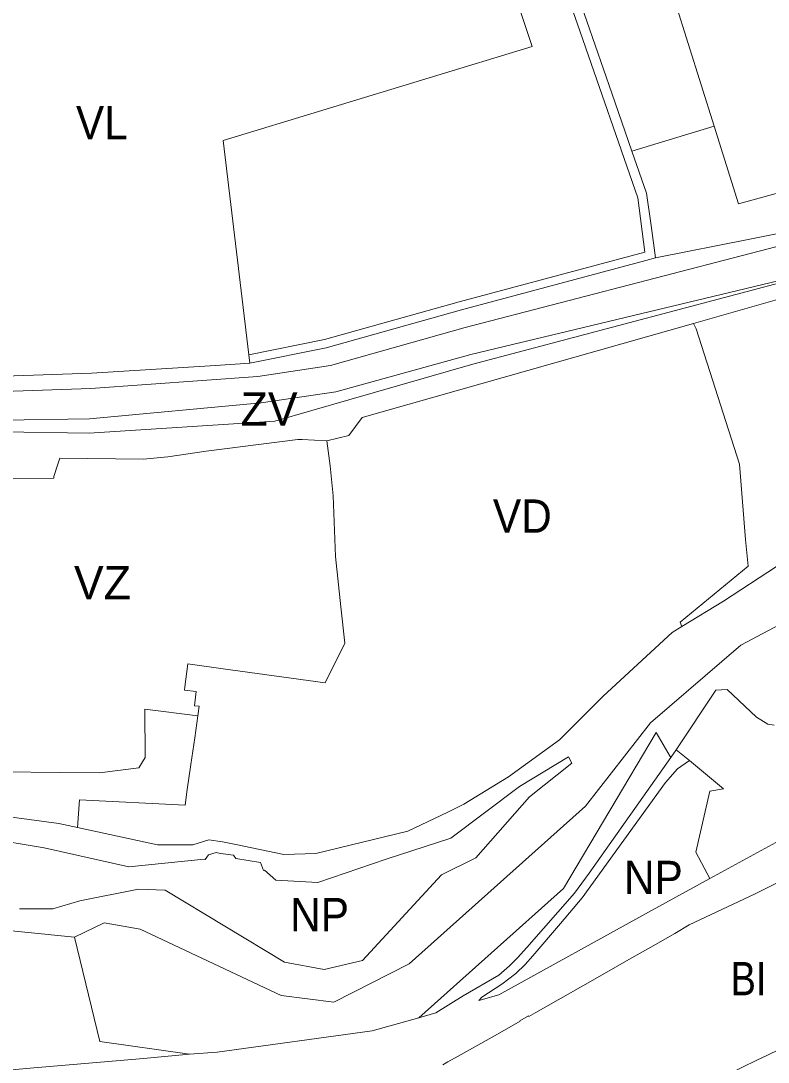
# Model space of a CAD drawing. Extents: x -650451 to -642268, y -1075216 to -1066610.
# Drawn here: x -646618.6 to -646349.6, y -1070484.4 to -1070109.3 of the extents above; entities that cross this region are included whole.
import ezdxf

# ---------------------------------------------------------------- set-up
doc = ezdxf.new("R2010")
doc.units = 0
doc.header["$LTSCALE"] = 4.8
for name, color, linetype, lineweight in [('15', 7, 'Continuous', 13), ('2', 7, 'Continuous', 13), ('31', 7, 'Continuous', 13), ('34', 7, 'Continuous', 13), ('35', 7, 'Continuous', 13), ('36', 7, 'Continuous', 13), ('40', 7, 'Continuous', 13), ('41', 7, 'Continuous', 13), ('45', 7, 'Continuous', 13), ('48', 7, 'Continuous', 13)]:
    doc.layers.add(name, color=color, linetype=linetype, lineweight=lineweight)
doc.layers.add('62', color=7, linetype='Continuous')

msp = doc.modelspace()

# ---------------------------------------------------------------- linework, layer by layer
at = {"layer": '15'}
for points in [[(-646536.47, -1070229.65), (-646509.31, -1070224.11), (-646460.8, -1070210.57), (-646393.97, -1070192.69), (-646396.51, -1070173.06), (-646417.23, -1070113.25), (-646424.17, -1070093.21), (-646446.21, -1070040.55), (-646450.22, -1070034.31), (-646445.81, -1070032.61)], [(-646445.81, -1070032.61), (-646420.85, -1070091.97), (-646405.85, -1070135.4), (-646398.64, -1070156.247)], [(-646173.2, -1070135.64), (-646227.29, -1070176.24), (-646274.26, -1070199.6), (-646291.14, -1070202.1), (-646315.95, -1070201.09), (-646376.5, -1070218.32)], [(-646398.64, -1070156.247), (-646393.4, -1070171.4), (-646391.75, -1070183.07), (-646390.1, -1070194.72)], [(-646705.52, -1070252.93), (-646625.33, -1070257.3), (-646594.04, -1070257.81), (-646527.17, -1070253.5), (-646500.57, -1070245.86), (-646455.89, -1070233.03), (-646311.02, -1070194.52)], [(-646390.1, -1070194.72), (-646393.58, -1070195.67), (-646459.99, -1070213.46), (-646508.71, -1070227.05), (-646536.11, -1070232.63), (-646536.47, -1070229.65)], [(-646376.5, -1070218.32), (-646495.71, -1070252.24), (-646500.58, -1070258.69), (-646508.45, -1070260.55)], [(-646508.45, -1070260.55), (-646517.36, -1070260.11), (-646518.94, -1070260.15), (-646551.91, -1070264.36), (-646565.72, -1070266.39), (-646574.52, -1070267.25), (-646604.59, -1070266.85), (-646605.28, -1070268.94), (-646606.76, -1070273.38), (-646606.75, -1070274.01), (-646653.15, -1070274.4), (-646660.11, -1070274.42), (-646660.07, -1070282.1), (-646649.84, -1070282.04), (-646649.55, -1070292.05)], [(-646647.05, -1070378.42), (-646647.02, -1070379.59), (-646604.46, -1070380.06), (-646590.31, -1070380.22), (-646576.16, -1070378.42), (-646573.88, -1070374.62), (-646574, -1070357.2), (-646554.86, -1070359.63)], [(-646554.86, -1070359.63), (-646556, -1070367.59), (-646557.42, -1070377.22), (-646558.74, -1070386.15), (-646559.41, -1070391.82), (-646597.44, -1070389.891), (-646598.16, -1070399.85)], [(-646370.56, -1070418.29), (-646344.26, -1070403.84), (-646336.35, -1070400.9), (-646225.15, -1070359.46)], [(-646475.345, -1070468.371), (-646469.235, -1070466.633), (-646459.41, -1070460.54), (-646446.59, -1070453), (-646442.72, -1070449.73), (-646439.83, -1070446.77), (-646436.48, -1070443.08), (-646419.34, -1070423.57), (-646414.01, -1070416.27), (-646384.62, -1070374.69), (-646382.67, -1070371.94), (-646377.86, -1070375.71)], [(-646377.86, -1070375.71), (-646378.32, -1070375.94), (-646382.19, -1070378.71), (-646386.6, -1070383.69), (-646416.56, -1070425.24), (-646424.34, -1070434.41), (-646434.35, -1070446.09), (-646437.1, -1070449.26), (-646440.39, -1070452.44), (-646445.45, -1070456.28), (-646452.6, -1070460.94), (-646453.736, -1070462.223), (-646446.536, -1070460.175), (-646392.61, -1070430.4), (-646370.56, -1070418.29)], [(-646598.16, -1070399.85), (-646604.96, -1070398.38), (-646641.54, -1070393.52), (-646652.04, -1070394.45)], [(-646325.23, -1070409.14), (-646354.31, -1070423.77), (-646378, -1070434.94), (-646383.22, -1070438.09), (-646391.82, -1070442.99), (-646400.54, -1070447.94), (-646404.52, -1070450.21), (-646413.57, -1070455.34), (-646433.25, -1070466.56), (-646435.74, -1070467.94), (-646435.86, -1070467.72), (-646438.98, -1070469.49), (-646438.88, -1070469.65), (-646446.97, -1070474.26), (-646461.19, -1070482.25), (-646464.9, -1070484.28), (-646466.68, -1070485.32)], [(-646557.82, -1070481.45), (-646547.87, -1070480.73), (-646492.113, -1070473.143), (-646475.345, -1070468.371)], [(-646364.46, -1070489.01), (-646353.63, -1070483.68), (-646350.05, -1070481.97), (-646336.58, -1070475.39)], [(-646653.92, -1070489.99), (-646646.34, -1070489.41), (-646617.87, -1070486.74), (-646616.63, -1070486.62), (-646574.42, -1070483.09), (-646557.82, -1070481.45)]]:
    msp.add_lwpolyline(points, dxfattribs=at)
at = {"layer": '2'}
for points in [[(-646466.68, -1070485.32), (-646464.9, -1070484.28), (-646461.19, -1070482.25), (-646446.97, -1070474.26), (-646438.88, -1070469.65), (-646438.98, -1070469.49), (-646435.86, -1070467.72), (-646435.74, -1070467.94), (-646433.25, -1070466.56), (-646413.57, -1070455.34), (-646404.52, -1070450.21), (-646400.54, -1070447.94), (-646391.82, -1070442.99), (-646383.22, -1070438.09), (-646378, -1070434.94), (-646354.31, -1070423.77), (-646325.23, -1070409.14)], [(-646336.58, -1070475.39), (-646350.05, -1070481.97), (-646353.63, -1070483.68), (-646364.46, -1070489.01)]]:
    msp.add_lwpolyline(points, dxfattribs=at)
at = {"layer": '31'}
for points in [[(-646369.042, -1070147.243), (-646383.07, -1070102.64), (-646400.77, -1070045.26), (-646401.69, -1070042.26), (-646409.27, -1070017.68)], [(-646215.99, -1070118.79), (-646225.41, -1070126.72), (-646245.94, -1070139.49), (-646266.83, -1070149.27), (-646298.56, -1070158.26), (-646360.23, -1070175.26), (-646369.042, -1070147.243)]]:
    msp.add_lwpolyline(points, dxfattribs=at)
at = {"layer": '34'}
for points in [[(-646409.27, -1070017.68), (-646401.69, -1070042.26), (-646400.77, -1070045.26), (-646383.07, -1070102.64), (-646369.042, -1070147.243), (-646398.64, -1070156.247)], [(-646398.64, -1070156.247), (-646405.85, -1070135.4), (-646420.85, -1070091.97), (-646445.81, -1070032.61)], [(-646461.415, -1070037.991), (-646434.503, -1070118.512), (-646545.78, -1070152.41), (-646536.47, -1070229.65), (-646536.11, -1070232.63)], [(-646536.11, -1070232.63), (-646548.56, -1070233.4), (-646593.13, -1070236.17), (-646624.5, -1070237.28), (-646651.86, -1070235.22)]]:
    msp.add_lwpolyline(points, dxfattribs=at)
at = {"layer": '35'}
for points in [[(-646508.45, -1070260.55), (-646500.58, -1070258.69), (-646495.71, -1070252.24), (-646376.5, -1070218.32)], [(-646376.5, -1070218.32), (-646375.52, -1070220.21), (-646359.89, -1070269.01), (-646357.73, -1070296.13), (-646356.8, -1070305.73), (-646381.25, -1070325.85), (-646380.69, -1070327.47)], [(-646554.86, -1070359.63), (-646554.42, -1070356.22), (-646556.1, -1070356), (-646555.42, -1070350.94), (-646559.71, -1070350.35), (-646559.55, -1070349.16), (-646558.49, -1070340.9), (-646545.77, -1070342.7), (-646509.08, -1070347.79), (-646501.94, -1070333.51), (-646503.36, -1070320.39), (-646505.33, -1070302.27), (-646506.17, -1070280.39), (-646507.27, -1070269.61), (-646508.45, -1070260.55)], [(-646380.69, -1070327.47), (-646384.18, -1070329.58), (-646408.97, -1070352.57), (-646422.07, -1070365.6), (-646424.74, -1070368.25), (-646443.05, -1070381.67), (-646459.18, -1070391.48), (-646464.85, -1070394.37), (-646479.26, -1070401.17), (-646512.38, -1070409.18), (-646523.89, -1070409.54), (-646541.25, -1070406.02), (-646545.97, -1070405.06), (-646550.91, -1070404.27), (-646556.66, -1070406.07), (-646569.39, -1070406.06), (-646598.16, -1070399.85)], [(-646598.16, -1070399.85), (-646597.44, -1070389.891), (-646559.41, -1070391.82), (-646558.74, -1070386.15), (-646557.42, -1070377.22), (-646556, -1070367.59), (-646554.86, -1070359.63)]]:
    msp.add_lwpolyline(points, dxfattribs=at)
at = {"layer": '36'}
for points in [[(-646649.55, -1070292.05), (-646649.84, -1070282.04), (-646660.07, -1070282.1), (-646660.11, -1070274.42), (-646653.15, -1070274.4), (-646606.75, -1070274.01), (-646606.76, -1070273.38), (-646605.28, -1070268.94), (-646604.59, -1070266.85), (-646574.52, -1070267.25), (-646565.72, -1070266.39), (-646551.91, -1070264.36), (-646518.94, -1070260.15), (-646517.36, -1070260.11), (-646508.45, -1070260.55)], [(-646508.45, -1070260.55), (-646507.27, -1070269.61), (-646506.17, -1070280.39), (-646505.33, -1070302.27), (-646503.36, -1070320.39), (-646501.94, -1070333.51), (-646509.08, -1070347.79), (-646545.77, -1070342.7), (-646558.49, -1070340.9), (-646559.55, -1070349.16), (-646559.71, -1070350.35), (-646555.42, -1070350.94), (-646556.1, -1070356), (-646554.42, -1070356.22), (-646554.86, -1070359.63)], [(-646554.86, -1070359.63), (-646574, -1070357.2), (-646573.88, -1070374.62), (-646576.16, -1070378.42), (-646590.31, -1070380.22), (-646604.46, -1070380.06), (-646647.02, -1070379.59), (-646647.05, -1070378.42)]]:
    msp.add_lwpolyline(points, dxfattribs=at)
at = {"layer": '40'}
for points in [[(-646167.42, -1070080.12), (-646188.23, -1070118.05), (-646222.67, -1070149.2), (-646253.56, -1070166.46), (-646458.66, -1070219.82), (-646507.14, -1070233.5), (-646533.27, -1070237.44), (-646593.37, -1070241.77), (-646624.73, -1070242.88), (-646662.64, -1070240.16), (-646715.61, -1070235.1), (-646724.37, -1070233.91), (-646728.78, -1070233.64)], [(-646390.1, -1070194.72), (-646356.23, -1070187.98), (-646313.92, -1070179.55), (-646253.56, -1070162.72), (-646229.39, -1070148.92), (-646196.87, -1070122), (-646193.22, -1070118.3), (-646167.42, -1070080.12)], [(-646721.7, -1070247.99), (-646715.71, -1070249.37), (-646664.55, -1070252.31), (-646625.16, -1070253.11), (-646593.82, -1070252.61), (-646532.07, -1070246.86), (-646505.17, -1070242.94), (-646456.64, -1070229.46), (-646311.02, -1070194.52)], [(-646311.02, -1070194.52), (-646455.89, -1070233.03), (-646500.57, -1070245.86), (-646527.17, -1070253.5), (-646594.04, -1070257.81), (-646625.33, -1070257.3), (-646705.52, -1070252.93)], [(-646536.11, -1070232.63), (-646508.71, -1070227.05), (-646459.99, -1070213.46), (-646393.58, -1070195.67), (-646390.1, -1070194.72)], [(-646651.86, -1070235.22), (-646624.5, -1070237.28), (-646593.13, -1070236.17), (-646548.56, -1070233.4), (-646536.11, -1070232.63)], [(-646695.27, -1070421.45), (-646676.15, -1070422.34), (-646666.47, -1070427.23), (-646664.64, -1070428.52), (-646650.57, -1070434.16), (-646599.32, -1070439.31)], [(-646599.32, -1070439.31), (-646590.18, -1070476.99), (-646557.82, -1070481.45)], [(-646557.82, -1070481.45), (-646574.42, -1070483.09), (-646616.63, -1070486.62), (-646617.87, -1070486.74), (-646646.34, -1070489.41), (-646653.92, -1070489.99)]]:
    msp.add_lwpolyline(points, dxfattribs=at)
at = {"layer": '41'}
for points in [[(-646475.345, -1070468.371), (-646423.26, -1070421.78), (-646389.93, -1070365.6), (-646384.85, -1070374.3), (-646384.62, -1070374.69)], [(-646384.62, -1070374.69), (-646414.01, -1070416.27), (-646419.34, -1070423.57), (-646436.48, -1070443.08), (-646439.83, -1070446.77), (-646442.72, -1070449.73), (-646446.59, -1070453), (-646459.41, -1070460.54), (-646469.235, -1070466.633), (-646475.345, -1070468.371)]]:
    msp.add_lwpolyline(points, dxfattribs=at)
at = {"layer": '45'}
for points in [[(-646728.78, -1070233.64), (-646724.37, -1070233.91), (-646715.61, -1070235.1), (-646662.64, -1070240.16), (-646624.73, -1070242.88), (-646593.37, -1070241.77), (-646533.27, -1070237.44), (-646507.14, -1070233.5), (-646458.66, -1070219.82), (-646253.56, -1070166.46), (-646222.67, -1070149.2), (-646188.23, -1070118.05), (-646167.42, -1070080.12)], [(-646046.84, -1070157.03), (-646047.97, -1070168.31), (-646058.29, -1070197.88), (-646062.69, -1070204.21), (-646072.06, -1070219.56), (-646104.49, -1070251.8), (-646145.19, -1070287.85), (-646168.86, -1070291.34), (-646203.06, -1070281.27), (-646228.96, -1070273.65), (-646235.69, -1070273.19), (-646240.68, -1070272.84), (-646265.2, -1070280.49), (-646302.98, -1070303.43), (-646313.77, -1070309.99), (-646359.41, -1070334.2), (-646391.97, -1070362.11), (-646415.34, -1070392.15), (-646478.77, -1070449), (-646505.87, -1070462.81), (-646524.86, -1070460.39), (-646575.64, -1070436.46), (-646588.54, -1070434.24), (-646599.32, -1070439.31)], [(-646311.02, -1070194.52), (-646456.64, -1070229.46), (-646505.17, -1070242.94), (-646532.07, -1070246.86), (-646593.82, -1070252.61), (-646625.16, -1070253.11), (-646664.55, -1070252.31), (-646715.71, -1070249.37), (-646721.7, -1070247.99), (-646728.78, -1070233.64)], [(-646380.69, -1070327.47), (-646365.63, -1070318.37), (-646346.57, -1070305.88), (-646321.24, -1070293.85), (-646259.91, -1070256.89), (-646246.71, -1070255.96), (-646245.02, -1070257.65), (-646234.17, -1070260.88), (-646233.69, -1070259.57), (-646210.38, -1070267.68)], [(-646598.16, -1070399.85), (-646569.39, -1070406.06), (-646556.66, -1070406.07), (-646550.91, -1070404.27), (-646545.97, -1070405.06), (-646541.25, -1070406.02), (-646523.89, -1070409.54), (-646512.38, -1070409.18), (-646479.26, -1070401.17), (-646464.85, -1070394.37), (-646459.18, -1070391.48), (-646443.05, -1070381.67), (-646424.74, -1070368.25), (-646422.07, -1070365.6), (-646408.97, -1070352.57), (-646384.18, -1070329.58), (-646380.69, -1070327.47)], [(-646619.03, -1070429.13), (-646607.05, -1070429.15), (-646597.37, -1070426.31), (-646576.22, -1070422.12), (-646566.58, -1070422.49), (-646523.66, -1070448.37), (-646509.42, -1070451.06), (-646495.62, -1070447.72), (-646467.23, -1070416.87), (-646454.82, -1070410.76), (-646435.48, -1070388.88), (-646420.24, -1070376.73), (-646421.46, -1070374.43), (-646439.06, -1070385.11), (-646463.79, -1070403.68), (-646487.05, -1070411.27), (-646511.67, -1070419.64), (-646526.78, -1070418.79), (-646530.91, -1070415.29), (-646531.24, -1070415.41), (-646532.26, -1070412.53), (-646541.17, -1070410.99), (-646542.07, -1070409.82), (-646546.67, -1070409.19), (-646548.23, -1070408.85), (-646551.02, -1070409.76), (-646552.27, -1070411.45), (-646552.55, -1070411.24), (-646579.69, -1070414.01), (-646610.18, -1070407.22), (-646631.77, -1070403.63)], [(-646652.04, -1070394.45), (-646641.54, -1070393.52), (-646604.96, -1070398.38), (-646598.16, -1070399.85)], [(-646599.32, -1070439.31), (-646650.57, -1070434.16), (-646664.64, -1070428.52), (-646666.47, -1070427.23), (-646676.15, -1070422.34), (-646695.27, -1070421.45)]]:
    msp.add_lwpolyline(points, dxfattribs=at)
at = {"layer": '48'}
for p, q in [((-646398.64, -1070156.247), (-646369.042, -1070147.243)), ((-646377.86, -1070375.71), (-646365.7, -1070385.89))]:
    msp.add_line(p, q, dxfattribs=at)
for points in [[(-646167.42, -1070080.12), (-646193.22, -1070118.3), (-646196.87, -1070122), (-646229.39, -1070148.92), (-646253.56, -1070162.72), (-646313.92, -1070179.55), (-646356.23, -1070187.98), (-646390.1, -1070194.72)], [(-646369.042, -1070147.243), (-646360.23, -1070175.26), (-646298.56, -1070158.26), (-646266.83, -1070149.27), (-646245.94, -1070139.49), (-646225.41, -1070126.72), (-646215.99, -1070118.79)], [(-646390.1, -1070194.72), (-646391.75, -1070183.07), (-646393.4, -1070171.4), (-646398.64, -1070156.247)], [(-646599.32, -1070439.31), (-646588.54, -1070434.24), (-646575.64, -1070436.46), (-646524.86, -1070460.39), (-646505.87, -1070462.81), (-646478.77, -1070449), (-646415.34, -1070392.15), (-646391.97, -1070362.11), (-646359.41, -1070334.2), (-646313.77, -1070309.99), (-646302.98, -1070303.43), (-646265.2, -1070280.49), (-646240.68, -1070272.84), (-646235.69, -1070273.19), (-646228.96, -1070273.65), (-646203.06, -1070281.27), (-646168.86, -1070291.34), (-646145.19, -1070287.85), (-646104.49, -1070251.8), (-646072.06, -1070219.56), (-646062.69, -1070204.21), (-646058.29, -1070197.88), (-646047.97, -1070168.31), (-646046.84, -1070157.03)], [(-646347.49, -1070363.01), (-646349.76, -1070362.69), (-646353.81, -1070360.18), (-646364.34, -1070350.19), (-646368.4, -1070350.41), (-646382.67, -1070371.94), (-646384.62, -1070374.69)], [(-646384.62, -1070374.69), (-646384.85, -1070374.3), (-646389.93, -1070365.6), (-646423.26, -1070421.78), (-646475.345, -1070468.371)], [(-646631.77, -1070403.63), (-646610.18, -1070407.22), (-646579.69, -1070414.01), (-646552.55, -1070411.24), (-646552.27, -1070411.45), (-646551.02, -1070409.76), (-646548.23, -1070408.85), (-646546.67, -1070409.19), (-646542.07, -1070409.82), (-646541.17, -1070410.99), (-646532.26, -1070412.53), (-646531.24, -1070415.41), (-646530.91, -1070415.29), (-646526.78, -1070418.79), (-646511.67, -1070419.64), (-646487.05, -1070411.27), (-646463.79, -1070403.68), (-646439.06, -1070385.11), (-646421.46, -1070374.43), (-646420.24, -1070376.73), (-646435.48, -1070388.88), (-646454.82, -1070410.76), (-646467.23, -1070416.87), (-646495.62, -1070447.72), (-646509.42, -1070451.06), (-646523.66, -1070448.37), (-646566.58, -1070422.49), (-646576.22, -1070422.12), (-646597.37, -1070426.31), (-646607.05, -1070429.15), (-646619.03, -1070429.13)], [(-646370.56, -1070418.29), (-646392.61, -1070430.4), (-646446.536, -1070460.175), (-646453.736, -1070462.223), (-646452.6, -1070460.94), (-646445.45, -1070456.28), (-646440.39, -1070452.44), (-646437.1, -1070449.26), (-646434.35, -1070446.09), (-646424.34, -1070434.41), (-646416.56, -1070425.24), (-646386.6, -1070383.69), (-646382.19, -1070378.71), (-646378.32, -1070375.94), (-646377.86, -1070375.71)], [(-646365.7, -1070385.89), (-646370.61, -1070386.73), (-646375.63, -1070408.76), (-646370.56, -1070418.29)], [(-646557.82, -1070481.45), (-646590.18, -1070476.99), (-646599.32, -1070439.31)], [(-646475.345, -1070468.371), (-646492.113, -1070473.143), (-646547.87, -1070480.73), (-646557.82, -1070481.45)]]:
    msp.add_lwpolyline(points, dxfattribs=at)

# ---------------------------------------------------------------- texts
at = {"layer": '62'}
for s, width, p in [('VL', 0.95, (-646598.745, -1070151.965)), ('VD', 0.95, (-646448.669, -1070293.705)), ('NP', 0.95, (-646401.492, -1070423.864)), ('NP', 0.95, (-646521.645, -1070437.242)), ('BI', 0.85, (-646363.113, -1070460.304))]:
    msp.add_text(s, height=12, dxfattribs=dict(at, width=width)).set_placement(p)
for s, p in [('ZV', (-646539.46, -1070255.105)), ('VZ', (-646599.458, -1070317.665))]:
    msp.add_text(s, height=12, dxfattribs=at).set_placement(p)

doc.saveas('drawing.dxf')
